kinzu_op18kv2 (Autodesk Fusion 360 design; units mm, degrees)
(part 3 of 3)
sketch "スケッチ105" plane through (0, 0, 0) normal (0, 0, 1) x axis (1, 0, 0)
  line L1 (0, -5) -> (0, -5)
  line L2 (-0.0003, 55.0002) -> (0, -10)
  line L3 (30.0001, -5) -> (0, -5)
  line L4 (0, -10) -> (30.0001, -10)
  line L5 (30.0001, 25) -> (0, 25)
  line L6 (30.0001, -10) -> (30.0001, 55.0001)
  line L7 (20, -10) -> (20, 55)
  line L8 (5, 55.0001) -> (30.0001, 5)
  line L9 (30.0001, 55.0001) -> (-0.0003, 55.0002)
  line L10 (2.5, -10) -> (30.0001, 45)
  curve K1 (0.5, 53.0557) -> (2.8, 53.0115)
  curve K2 (2.8, 53.0115) -> (23.0212, 47.1804)
  curve K3 (23.0212, 47.1804) -> (25.7991, 44.5)
  curve K4 (25.7991, 44.5) -> (28.1535, 40.4198)
  curve K5 (28.1535, 40.4198) -> (28.8559, 1)
  line L11 (0, 53.0557) -> (0.5, 53.0557)
  curve K6 (26.2794, 39.7214) -> (26.8563, 0.959)
  curve K7 (24.2454, 43.2407) -> (26.2794, 39.7214)
  curve K8 (21.7981, 45.598) -> (24.2454, 43.2407)
  curve K9 (2.7324, 51.0126) -> (21.7981, 45.598)
  curve K10 (0.4945, 51.0557) -> (2.7324, 51.0126)
  line L12 (0, 51.0557) -> (0.4945, 51.0557)
  line L13 (3.9, 40) -> (3.9, 26.5)
  curve K11 (0.5, 41.9835) -> (3.9, 40)
  line L14 (0.5, 48.5762) -> (0.5, 41.9835)
  line L15 (0.5, 50.3065) -> (0.5, 48.5762)
  line L16 (0.5, 53.0557) -> (0.5, 50.3065)
  curve K12 (3.9, 26.5) -> (0.5, 24.5165)
  line L17 (0.5, 24.5165) -> (0.5, 1)
  line L18 (1.9, 23.3085) -> (1.9, 1)
  curve K13 (5.3, 26.5) -> (1.9, 23.3085)
  line L19 (5.3, 40) -> (5.3, 26.5)
  curve K14 (1.9, 43.1915) -> (5.3, 40)
  line L20 (1.9, 48.5762) -> (1.9, 43.1915)
  line L21 (1.9, 55.0002) -> (1.9, 48.5762)
  line L22 (18.8, -10) -> (18.8, 55)
  line L23 (3.9267, 54.4635) -> (30.0001, 2.3167)
  line L24 (1.4267, -9.4633) -> (28.9268, 45.5367)
  line L25 (30.0001, -2) -> (-0.0001, -2)
  line L26 (-0.0003, 55.0001) -> (0, 55.0001)
  line L27 (-0.0002, 25) -> (0, 25)
  line L28 (-3.9005, 40) -> (-3.9003, 26.5)
  line L29 (-0.0003, 55.0002) -> (0, -10)
  line L30 (-30.0004, 24.9997) -> (-0.0003, 25)
  line L31 (-3.9273, 54.4634) -> (-30.0002, 2.3164)
  line L32 (-5.3005, 39.9999) -> (-5.3003, 26.4999)
  curve K15 (-3.9003, 26.5) -> (-0.5003, 24.5165)
  line L33 (-30.0001, -2.0003) -> (0, -2)
  line L34 (-30, -10.0003) -> (-30.0007, 54.9998)
  line L35 (-5.0006, 55.0001) -> (-30.0002, 4.9997)
  line L36 (-0.5003, 24.5165) -> (-0.5001, 1)
  line L37 (-0.5006, 50.3065) -> (-0.5005, 48.5762)
  line L38 (-0.5005, 48.5762) -> (-0.5005, 41.9835)
  line L39 (-0.0006, 51.0557) -> (-0.495, 51.0557)
  line L40 (-1.9006, 55.0002) -> (-1.9005, 48.5761)
  curve K16 (-0.5006, 53.0557) -> (-2.8006, 53.0115)
  line L41 (-1.9005, 48.5761) -> (-1.9005, 43.1915)
  line L42 (-0.0003, 55.0001) -> (-0.0006, 55.0001)
  curve K17 (-0.495, 51.0557) -> (-2.7329, 51.0126)
  line L43 (-0.5006, 53.0557) -> (-0.5006, 50.3065)
  line L44 (0, -10) -> (-30, -10.0003)
  curve K18 (-1.9005, 43.1915) -> (-5.3005, 39.9999)
  curve K19 (-24.2458, 43.2405) -> (-26.2798, 39.7211)
  line L45 (-0.0006, 53.0557) -> (-0.5006, 53.0557)
  line L46 (0, -5) -> (0, -5)
  curve K20 (-2.7329, 51.0126) -> (-21.7986, 45.5978)
  curve K21 (-26.2798, 39.7211) -> (-26.8564, 0.9587)
  line L47 (-30.0001, -5.0003) -> (0, -5)
  curve K22 (-0.5005, 41.9835) -> (-3.9005, 40)
  curve K23 (-25.7996, 44.4997) -> (-28.1539, 40.4195)
  line L48 (-30.0007, 54.9998) -> (-0.0003, 55.0002)
  curve K24 (-21.7986, 45.5978) -> (-24.2458, 43.2405)
  curve K25 (-23.0217, 47.1802) -> (-25.7996, 44.4997)
  curve K26 (-2.8006, 53.0115) -> (-23.0217, 47.1802)
  line L49 (-2.5, -10) -> (-30.0006, 44.9997)
  curve K27 (-28.1539, 40.4195) -> (-28.856, 0.9997)
  line L50 (-0.0002, 25) -> (-0.0003, 25)
  line L51 (-18.8, -10.0002) -> (-18.8006, 54.9998)
  line L52 (-20, -10.0002) -> (-20.0006, 54.9998)
  line L53 (-1.9003, 23.3085) -> (-1.9001, 1)
  curve K28 (-5.3003, 26.4999) -> (-1.9003, 23.3085)
  line L54 (-1.4267, -9.4634) -> (-28.9273, 45.5364)
  line L55 (-30.0002, 0.9994) -> (30.0001, 1)
  line L56 (1.9, -0.7414) -> (1.9, 1)
  line L57 (-1.9, -0.8805) -> (-1.9001, 1)
  point P18 (0.5, 53.0557)
  point P23 (0.5, 53.0557)
  point P32 (30.0001, 5)
  point P33 (30.0001, 45)
  point P48 (1.9, 55.0002)
  point P55 (30.0001, 2.3167)
  point P57 (30.0001, -2)
  point P58 (-0.0002, 25)
  point P59 (0, -5)
  point P60 (-0.0003, 55.0001)
  point P1 (0, 0)
  point P115 (-0.0001, 0)
  point P2 (0, 55.0001)
  point P99 (-0.0006, 55.0001)
  point P3 (0, 25)
  point P94 (-0.0003, 25)
  point P4 (0, -5)
  point P111 (0, -5)
  point P5 (20, 55)
  point P116 (-20.0006, 54.9998)
  point P6 (20, -10)
  point P108 (-20, -10.0002)
  point P7 (0, 25)
  point P114 (-0.0003, 25)
  point P8 (0, -10)
  point P113 (0, -10)
  point P9 (30.0001, 55.0001)
  point P118 (-30.0007, 54.9998)
  point P10 (30.0001, 25)
  point P76 (-30.0004, 24.9997)
  point P11 (30.0001, -10)
  point P64 (-30, -10.0003)
  point P12 (30.0001, -5)
  point P109 (-30.0001, -5.0003)
  point P13 (0, 0)
  point P112 (-0.0001, 0)
  point P14 (-0.0003, 55.0002)
  point P63 (-0.0003, 55.0002)
  point P15 (0, -5)
  point P77 (0, -5)
  point P16 (5, 55.0001)
  point P84 (-5.0006, 55.0001)
  point P17 (2.8, 53.0115)
  point P95 (-2.8006, 53.0115)
  point P74 (-0.5006, 53.0557)
  point P19 (23.0212, 47.1804)
  point P107 (-23.0217, 47.1802)
  point P20 (25.7991, 44.5)
  point P119 (-25.7996, 44.4997)
  point P21 (28.1535, 40.4198)
  point P73 (-28.1539, 40.4195)
  point P22 (28.8559, 1)
  point P80 (-28.856, 0.9997)
  point P97 (-0.5006, 53.0557)
  point P24 (0, 53.0557)
  point P100 (-0.0006, 53.0557)
  point P25 (26.8563, 0.959)
  point P120 (-26.8564, 0.9587)
  point P26 (26.2794, 39.7214)
  point P85 (-26.2798, 39.7211)
  point P27 (24.2454, 43.2407)
  point P86 (-24.2458, 43.2405)
  point P28 (21.7981, 45.598)
  point P117 (-21.7986, 45.5978)
  point P29 (2.7324, 51.0126)
  point P104 (-2.7329, 51.0126)
  point P30 (0.4945, 51.0557)
  point P101 (-0.495, 51.0557)
  point P31 (0, 51.0557)
  point P78 (-0.0006, 51.0557)
  point P70 (-30.0002, 4.9997)
  point P71 (-30.0006, 44.9997)
  point P34 (3.9, 26.5)
  point P92 (-3.9003, 26.5)
  point P35 (3.9, 40)
  point P79 (-3.9005, 40)
  point P36 (0.5, 41.9835)
  point P89 (-0.5005, 41.9835)
  point P37 (0.5, 48.5762)
  point P75 (-0.5005, 48.5762)
  point P38 (0.5, 48.5762)
  point P96 (-0.5005, 48.5762)
  point P39 (0.5, 50.3065)
  point P103 (-0.5006, 50.3065)
  point P40 (0.5, 24.5165)
  point P88 (-0.5003, 24.5165)
  point P41 (0.5, 1)
  point P102 (-0.5001, 1)
  point P42 (1.9, 1)
  point P87 (-1.9001, 1)
  point P43 (1.9, 23.3085)
  point P82 (-1.9003, 23.3085)
  point P44 (5.3, 26.5)
  point P105 (-5.3003, 26.4999)
  point P45 (5.3, 40)
  point P91 (-5.3005, 39.9999)
  point P46 (1.9, 43.1915)
  point P98 (-1.9005, 43.1915)
  point P47 (1.9, 48.5762)
  point P69 (-1.9005, 48.5761)
  point P68 (-1.9006, 55.0002)
  point P49 (18.8, 55)
  point P90 (-18.8006, 54.9998)
  point P50 (18.8, -10)
  point P106 (-18.8, -10.0002)
  point P51 (3.9267, 54.4635)
  point P93 (-3.9273, 54.4634)
  point P52 (2.5, -10)
  point P110 (-2.5, -10)
  point P53 (28.9268, 45.5367)
  point P81 (-28.9273, 45.5364)
  point P54 (1.4267, -9.4633)
  point P83 (-1.4267, -9.4634)
  point P67 (-30.0002, 2.3164)
  point P56 (-0.0001, -2)
  point P72 (0, -2)
  point P66 (-30.0001, -2.0003)
  point P65 (-0.0002, 25)
  point P62 (0, -5)
  point P61 (-0.0003, 55.0001)
  point P121 (30.0001, 1)
  point P122 (-30.0002, 0.9994)
  horizontal L26
  coincident P18 P23
  coincident L6 P32
  coincident L6 P33
  coincident L9 P48
  perpendicular L9 L21
  coincident L6 P55
  coincident L6 P57
  perpendicular L6 L25
  coincident L2 P58
  coincident L2 P59
  coincident L2 P60
  symmetric P1 L2 P115
  symmetric P2 L2 P99
  symmetric P3 L2 P94
  symmetric P4 L2 P111
  symmetric P5 L2 P116
  symmetric P6 L2 P108
  symmetric P7 L2 P114
  symmetric P8 L2 P113
  symmetric P9 L2 P118
  symmetric P10 L2 P76
  symmetric P11 L2 P64
  symmetric P12 L2 P109
  symmetric P13 L2 P112
  symmetric P14 L2 P63
  symmetric P15 L2 P77
  symmetric P16 L2 P84
  symmetric L2 P17 P95
  symmetric L2 P18 P74
  symmetric L2 K1 K16
  symmetric L2 P19 P107
  symmetric L2 K2 K26
  symmetric L2 P20 P119
  symmetric L2 K3 K25
  symmetric L2 P21 P73
  symmetric L2 K4 K23
  symmetric L2 P22 P80
  symmetric L2 K5 K27
  symmetric L2 P23 P97
  symmetric L2 P24 P100
  symmetric L2 P25 P120
  symmetric L2 P26 P85
  symmetric L2 K6 K21
  symmetric L2 P27 P86
  symmetric L2 K7 K19
  symmetric L2 P28 P117
  symmetric L2 K8 K24
  symmetric L2 P29 P104
  symmetric L2 K9 K20
  symmetric L2 P30 P101
  symmetric L2 K10 K17
  symmetric L2 P31 P78
  symmetric L2 P32 P70
  symmetric L2 P33 P71
  symmetric L2 P34 P92
  symmetric L2 P35 P79
  symmetric L2 P36 P89
  symmetric L2 K11 K22
  symmetric L2 P37 P75
  symmetric L2 P38 P96
  symmetric L2 P39 P103
  symmetric L2 P40 P88
  symmetric L2 K12 K15
  symmetric L2 P41 P102
  symmetric L2 P42 P87
  symmetric L2 P43 P82
  symmetric L2 P44 P105
  symmetric L2 K13 K28
  symmetric L2 P45 P91
  symmetric L2 P46 P98
  symmetric L2 K14 K18
  symmetric L2 P47 P69
  symmetric L2 P48 P68
  symmetric L2 P49 P90
  symmetric L2 P50 P106
  symmetric L2 P51 P93
  symmetric L2 P52 P110
  symmetric L2 P53 P81
  symmetric L2 P54 P83
  symmetric L2 P55 P67
  symmetric L2 P56 P72
  symmetric L2 P57 P66
  symmetric L2 P58 P65
  symmetric L2 P59 P62
  symmetric L2 P60 P61
  coincident L6 P121
  coincident L34 P122
  perpendicular L34 L55
  perpendicular L25 L56
  perpendicular L55 L57
  dimension "d1525" = -2
  dimension "d1526" = 1.4
  dimension "d1527" = 1.2
  dimension "d1529" = 1.2
extrude "押し出し250" cut sketch "スケッチ105" profile of L5 L7 L8 L10 K6 K7 K8 K9 K10 L18 K13 L20 L19 K14 L21 L22 L23 L24 L30 L31 L32 L35 L40 L41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 along normal blind 49.515
combine "結合73" bodies "MB2 (1)", "MB2"
fillet "フィレット10" radius 1 1
sketch "スケッチ103" plane through (0, 5.1358, -1.8693) normal (0, -0.9397, 0.342) x axis (1, 0, 0)
  line L1 (-14.3, 21.378) -> (-19.5, 21.378)
  line L2 (-14.3, 23.378) -> (-14.3, 21.378)
  line L3 (-19.5, 23.378) -> (-14.3, 23.378)
  line L4 (-19.5, 21.378) -> (-19.5, 23.378)
  line L5 (-19.5, 23.378) -> (-19.5, 17.578)
  line L6 (-19.25, 23.378) -> (-19.25, 17.578)
  line L7 (-19.75, 23.378) -> (-19.75, 17.578)
  line L8 (-19.75, 17.578) -> (-19.25, 17.578)
  line L9 (-19.75, 23.378) -> (-19.25, 23.378)
  line L10 (-19.5, 22.878) -> (-14.3, 22.878)
  line L11 (-14.8, 23.378) -> (-14.8, 21.378)
  line L12 (-16.8, 23.378) -> (-16.8, 21.378)
  line L13 (-17.3, 23.378) -> (-17.3, 21.378)
  perpendicular L7 L8
  perpendicular L7 L9
  dimension "d1458" = 0.25
  dimension "d1459" = -0.25 (= "-d1458")
  dimension "d1460" = -0.5
  dimension "d1461" = -0.5
  dimension "d1462" distance L11 = -2
  dimension "d1463" = -0.5
extrude "押し出し239" new body sketch "スケッチ103" blind 7.943 from offset -0.5
sketch "スケッチ112" plane through (-19.25, 0, 0) normal (1, 0, 0) x axis (0, 1, 0)
  line L1 (11.6177, 14.4777) -> (4.1537, 17.1943)
  line L2 (13.4304, 19.458) -> (11.6177, 14.4777)
  line L3 (5.9664, 22.1747) -> (13.4304, 19.458)
  line L4 (12.9174, 18.0485) -> (5.4534, 20.7652)
  line L5 (13.6014, 19.9279) -> (12.9174, 18.0485)
  line L6 (6.1374, 22.6445) -> (13.6014, 19.9279)
  line L7 (13.6014, 19.9279) -> (6.1374, 22.6445)
  line L8 (11.6177, 14.4777) -> (13.6014, 19.9279)
  line L9 (4.1537, 17.1943) -> (11.6177, 14.4777)
  line L10 (13.1315, 20.0989) -> (12.4475, 18.2195)
  line L11 (12.4475, 18.2195) -> (13.1315, 20.0989)
  line L12 (4.5203, 5.1837) -> (13.1315, 20.0989)
  line L13 (30.4199, 20.0989) -> (13.1315, 20.0989)
  line L14 (4.1537, 17.1943) -> (5.9664, 22.1747)
  line L15 (5.4534, 20.7652) -> (6.1374, 22.6445)
  line L16 (6.1374, 22.6445) -> (4.1537, 17.1943)
  point P15 (13.1315, 20.0989)
  point P16 (13.1315, 20.0989)
  horizontal L13
  coincident P15 P16
  dimension "d1620" angle L12 L13 = 120
extrude "押し出し263" cut sketch "スケッチ112" profile of L1 L3 L4 L6 L15 L16 L7 L9 L12 L14 distance 5.758
extrude "押し出し264" add of existing geometry to an object
combine "結合78"
sketch "スケッチ119" plane through (0, 0, 0) normal (1, 0, 0) x axis (0, 1, 0)
  curve K1 (-5.8864, 26.1954) -> (-2.3716, 23.3236)
  curve K2 (-2.3716, 23.3236) -> (-1.126, 23.1619)
  curve K3 (-1.126, 23.1619) -> (1.1397, 22.7897)
  curve K4 (1.1397, 22.7897) -> (-3.0129, 25.8163)
  curve K5 (-3.0129, 25.8163) -> (-4.2929, 27.1502)
  curve K6 (-4.2929, 27.1502) -> (-5.8864, 26.1954)
  curve K7 (-2.3716, 23.3236) -> (3.2322, 20.7143)
  curve K8 (3.2322, 20.7143) -> (39.9165, 7.6035)
  curve K9 (39.9951, 9.1347) -> (39.9165, 7.6035)
  curve K10 (39.9951, 9.1347) -> (2.6828, 22.3363)
  curve K11 (2.6828, 22.3363) -> (1.1397, 22.7897)
  curve K12 (-1.126, 23.1619) -> (1.1397, 22.7897)
  curve K13 (-2.3716, 23.3236) -> (-1.126, 23.1619)
  line L1 (-1, 39) -> (7, 39)
  line L2 (-1, -6) -> (-1, 39)
  line L3 (7, -6) -> (-1, -6)
  line L4 (7, 39) -> (7, -6)
  line L5 (1, 22) -> (7.5, 20.5)
  line L6 (-0.5, 23.5) -> (1, 22)
  line L7 (-0.5, 23.7551) -> (-0.5, 23.5)
  horizontal L1
  vertical L2
  horizontal L3
  vertical L4
  vertical L7
extrude "押し出し266" cut sketch "スケッチ119" profile of K3 K4 K10 K11 K12 L4 L5 L6 L7 distance 32.044
chamfer "面取り13" distance 8.482 Rotate Angle 45
draft "勾配2" Angle1 20 Angle2 0
draft "勾配3" Angle1 20 Angle2 0
draft "勾配4" Angle1 20 Angle2 0
draft "勾配5" Angle1 20 Angle2 0
draft "勾配6" Angle1 20 Angle2 0
mirror "ミラー21" mirrorStitchTolerance 0.1
fillet "フィレット11" radius 4
extrude "押し出し233" cut sketch "スケッチ5" along normal blind 0.8
combine "結合71" bodies "rib_b", "screw_b"
sketch "スケッチ106" plane through (0, 6.012, 16.5179) normal (0, -0.342, -0.9397) x axis (1, 0, 0)
  line L1 (-18.7, -25.9904) -> (-19.5, -25.1904)
  line L2 (-19.5, -26.7904) -> (-18.7, -25.9904)
  line L3 (-20.3, -25.9904) -> (-19.5, -26.7904)
  line L4 (-19.5, -25.1904) -> (-20.3, -25.9904)
  line L5 (19.5, -25.1904) -> (18.7, -25.9904)
  line L6 (20.3, -25.9904) -> (19.5, -25.1904)
  line L7 (19.5, -26.7904) -> (20.3, -25.9904)
  line L8 (18.7, -25.9904) -> (19.5, -26.7904)
  line L9 (19.5, -8.5904) -> (20.3, -7.7904)
  line L10 (18.7, -7.7904) -> (19.5, -8.5904)
  line L11 (19.5, -6.9904) -> (18.7, -7.7904)
  line L12 (20.3, -7.7904) -> (19.5, -6.9904)
  line L13 (-20.3, -7.7904) -> (-19.5, -8.5904)
  line L14 (-19.5, -6.9904) -> (-20.3, -7.7904)
  line L15 (-18.7, -7.7904) -> (-19.5, -6.9904)
  line L16 (-19.5, -8.5904) -> (-18.7, -7.7904)
  line L17 (-19.7, -23.674) -> (-19.7, -10.1068)
  line L18 (-19.3, -10.1068) -> (-19.3, -23.674)
  line L19 (-19.25, -4.4427) -> (-19.25, -5.4789)
  line L20 (-19.75, -5.4789) -> (-19.75, -4.4427)
  line L21 (-20.3, -7.7904) -> (-19.5, -8.5904)
  line L22 (-19.5, -6.9904) -> (-20.3, -7.7904)
  line L23 (-18.7, -7.7904) -> (-19.5, -6.9904)
  line L24 (-19.5, -8.5904) -> (-18.7, -7.7904)
  line L25 (19.3, -23.674) -> (19.3, -10.1068)
  line L26 (19.7, -10.1068) -> (19.7, -23.674)
  line L27 (19.75, -4.4427) -> (19.75, -5.4789)
  line L28 (19.25, -5.4789) -> (19.25, -4.4427)
  line L29 (19.5, -8.5904) -> (20.3, -7.7904)
  line L30 (18.7, -7.7904) -> (19.5, -8.5904)
  line L31 (19.5, -6.9904) -> (18.7, -7.7904)
  line L32 (20.3, -7.7904) -> (19.5, -6.9904)
  line L33 (-50, 0) -> (50, 0)
  line L34 (-19.75, -4.4427) -> (-19.25, -4.4427)
  line L35 (19.25, -4.4427) -> (19.75, -4.4427)
  line L36 (19.3, -23.674) -> (19.3, -10.1068)
  line L37 (19.7, -10.1068) -> (19.7, -23.674)
  line L38 (19.75, -4.4427) -> (19.75, -5.4789)
  line L39 (19.25, -4.4427) -> (19.75, -4.4427)
  line L40 (19.25, -5.4789) -> (19.25, -4.4427)
  line L41 (19.5, -25.1904) -> (18.7, -25.9904)
  line L42 (20.3, -25.9904) -> (19.5, -25.1904)
  line L43 (19.5, -26.7904) -> (20.3, -25.9904)
  line L44 (18.7, -25.9904) -> (19.5, -26.7904)
  line L45 (-19.7, -23.674) -> (-19.7, -10.1068)
  line L46 (-19.3, -10.1068) -> (-19.3, -23.674)
  line L47 (-19.25, -4.4427) -> (-19.25, -5.4789)
  line L48 (-19.75, -4.4427) -> (-19.25, -4.4427)
  line L49 (-19.75, -5.4789) -> (-19.75, -4.4427)
  line L50 (-18.7, -25.9904) -> (-19.5, -25.1904)
  line L51 (-19.5, -26.7904) -> (-18.7, -25.9904)
  line L52 (-20.3, -25.9904) -> (-19.5, -26.7904)
  line L53 (-19.5, -25.1904) -> (-20.3, -25.9904)
  line L54 (-19.6, -23.7676) -> (-19.6, -10.0131)
  line L55 (-19.4, -10.0131) -> (-19.4, -23.7676)
  line L56 (-19.35, -4.5427) -> (-19.35, -5.5705)
  line L57 (-19.65, -4.5427) -> (-19.35, -4.5427)
  line L58 (-19.65, -5.5705) -> (-19.65, -4.5427)
  line L59 (19.65, -4.5427) -> (19.65, -5.5705)
  line L60 (19.35, -4.5427) -> (19.65, -4.5427)
  line L61 (19.35, -5.5705) -> (19.35, -4.5427)
  line L62 (19.4, -23.7676) -> (19.4, -10.0131)
  line L63 (19.6, -10.0131) -> (19.6, -23.7676)
  arc A1 centre (-19.5, -7.7904) radius 2.325 clockwise from (-19.7, -10.1068) to (-19.75, -5.4789)
  arc A2 centre (-19.5, -7.7904) radius 2.325 clockwise from (-19.7, -10.1068) to (-19.75, -5.4789)
  arc A3 centre (-19.5, -25.9904) radius 2.325 clockwise from (-19.3, -23.674) to (-19.7, -23.674)
  arc A4 centre (-19.5, -7.7904) radius 2.325 clockwise from (-19.25, -5.4789) to (-19.3, -10.1068)
  arc A5 centre (19.5, -7.7904) radius 2.325 clockwise from (19.3, -10.1068) to (19.25, -5.4789)
  arc A6 centre (19.5, -25.9904) radius 2.325 clockwise from (19.7, -23.674) to (19.3, -23.674)
  arc A7 centre (19.5, -7.7904) radius 2.325 clockwise from (19.75, -5.4789) to (19.7, -10.1068)
  arc A8 centre (19.5, -7.7904) radius 2.325 clockwise from (19.3, -10.1068) to (19.25, -5.4789)
  arc A9 centre (19.5, -25.9904) radius 2.325 clockwise from (19.7, -23.674) to (19.3, -23.674)
  arc A10 centre (19.5, -7.7904) radius 2.325 clockwise from (19.75, -5.4789) to (19.7, -10.1068)
  arc A11 centre (-19.5, -25.9904) radius 2.325 clockwise from (-19.3, -23.674) to (-19.7, -23.674)
  arc A12 centre (-19.5, -7.7904) radius 2.325 clockwise from (-19.25, -5.4789) to (-19.3, -10.1068)
  arc A13 centre (-19.5, -7.7904) radius 2.225 clockwise from (-19.6, -10.0131) to (-19.65, -5.5705)
  arc A14 centre (-19.5, -25.9904) radius 2.225 clockwise from (-19.4, -23.7676) to (-19.6, -23.7676)
  arc A15 centre (-19.5, -7.7904) radius 2.225 clockwise from (-19.35, -5.5705) to (-19.4, -10.0131)
  arc A16 centre (19.5, -7.7904) radius 2.225 clockwise from (19.65, -5.5705) to (19.6, -10.0131)
  arc A17 centre (19.5, -7.7904) radius 2.225 clockwise from (19.4, -10.0131) to (19.35, -5.5705)
  arc A18 centre (19.5, -25.9904) radius 2.225 clockwise from (19.6, -23.7676) to (19.4, -23.7676)
  perpendicular L20 L33
  dimension "d1536" = -0.1
  dimension "d1632" = -0.1
extrude "押し出し252" cut sketch "スケッチ106" profile of A2 A5 A8 A1 A13 L17 A3 L18 A4 L19 L20 L25 A6 L26 A7 L27 L28 L34 L35 L36 A9 L37 A10 L38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 to an object
chamfer "面取り14" distance 0.5 distance 0.4
fillet "フィレット12" radius 3 1
offset_faces "面をオフセット22" distance -0.3
fillet "フィレット13" radius 0.6
offset_faces "面をオフセット21" distance -0.15
offset_faces "面をオフセット20" distance -0.2
offset_faces "面をオフセット24" distance -0.2
offset_faces "面をオフセット23" distance 0.4
fillet "フィレット15" radius 0.3
offset_faces "面をオフセット25" distance -0.25
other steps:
derived_base_feature "派生した基準フィーチャ" bodies "pcb", "switch", "conn"
base_feature "基準フィーチャ6" bodies "surface_2"
base_feature "基準フィーチャ7" bodies "surface_1", "surface_1_extend"
base_feature "基準フィーチャ13" bodies "surface_2", "surface_2_extend"
base_feature "基準フィーチャ18" bodies "box (2)", "box_surface_in"
base_feature "基準フィーチャ8" bodies "box", "box_1_1.2mm"
base_feature "基準フィーチャ21" bodies "box_surface_in", "box_1_0.6mm"
base_feature "基準フィーチャ23" bodies "box_surface_in (1)", "box_1_2.5mm"
base_feature "基準フィーチャ14" bodies "box (1)", "box_2_1.5mm"
base_feature "基準フィーチャ17" bodies "box_1_0-1.2mm", "box_2_0-1.5mm", "main", "box_2_0-1.5mm (1)"
base_feature "基準フィーチャ25" bodies "main", "main (1)"
base_feature "基準フィーチャ22" bodies "box_1_0.6mm", "box_1_0.6mm (1)"
base_feature "基準フィーチャ24" bodies "box_1_0-2.5mm", "MB2"
create_component "CreateComponent1"
create_component "CreateComponent2" sketch "スケッチ1"
create_component "CreateComponent3"
create_component "CreateComponent4"
create_component "CreateComponent5"
create_component "CreateComponent7"
create_component "CreateComponent8"
create_component "CreateComponent9"
create_component "CreateComponent10"
create_component "CreateComponent1"
create_component "CreateComponent14"
named bodies: "surface", "lens", "around_lens", "main_pcb", "sensor", "zh_rmb", "zh_usb", "zh_lmb", "zh_side", "LED", "dpi_sw", "whl_sw", "whl_ec", "wheel", "wheel_ring", "switch", "conn", "pcb", "switch5", "switch4", "surface_2", "surface_mid", "surface_bot", "surface_1", "surface_1_extend", "surface_1_ext_1.2mm", "box", "box_1_1.2mm", "box_1_out", "box_1_0-1.2mm", "surface_2_extend", "surface_2_ext_1.5mm", "box (1)", "box_2_1.5mm", "box_2_out", "box_2_0-1.5mm", "box_bot_2mm_in", "box_bot_2mm_out", "main", "box_2_0-1.5mm (1)", "box (2)", "box_surface_in", "box_surface_out", "whl_L", "bush_mawari", "whl_R", "feet", "screw_b", "rib_b", "surface_1_ext_0.6mm", "box_1_0.6mm", "box_1_0-0.6mm", "box_1_0.6mm (1)", "rib_b (1)", "rib_b (2)", "rib_b (1) (1)", "surface_1_ext_2.5mm", "box_surface_in (1)", "box_1_2.5mm", "box_1_0-2.5mm"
